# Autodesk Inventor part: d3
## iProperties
Created: 2002-02
Part Number: d3
Document SubType Name: ﾓﾃﾞﾘﾝｸﾞ
Designer: Administrator
Control State: 0
Master: False
Checked Out: False
Shininess: 64.0
Length Units: 11269
Angle Units: 11279
Time Units: 11290
Mass Units: 11284
Length Display Precision: 2
Angle Display Precision: 1
Density: 0.0
Volumn: 0.0
Area: 0.0
PropertySet Name: Model Information
Author: Administrator
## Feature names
1. 押し出し4 [Extrusion]
2. 押し出し5 [Extrusion]
3. 穴1 [Hole]
